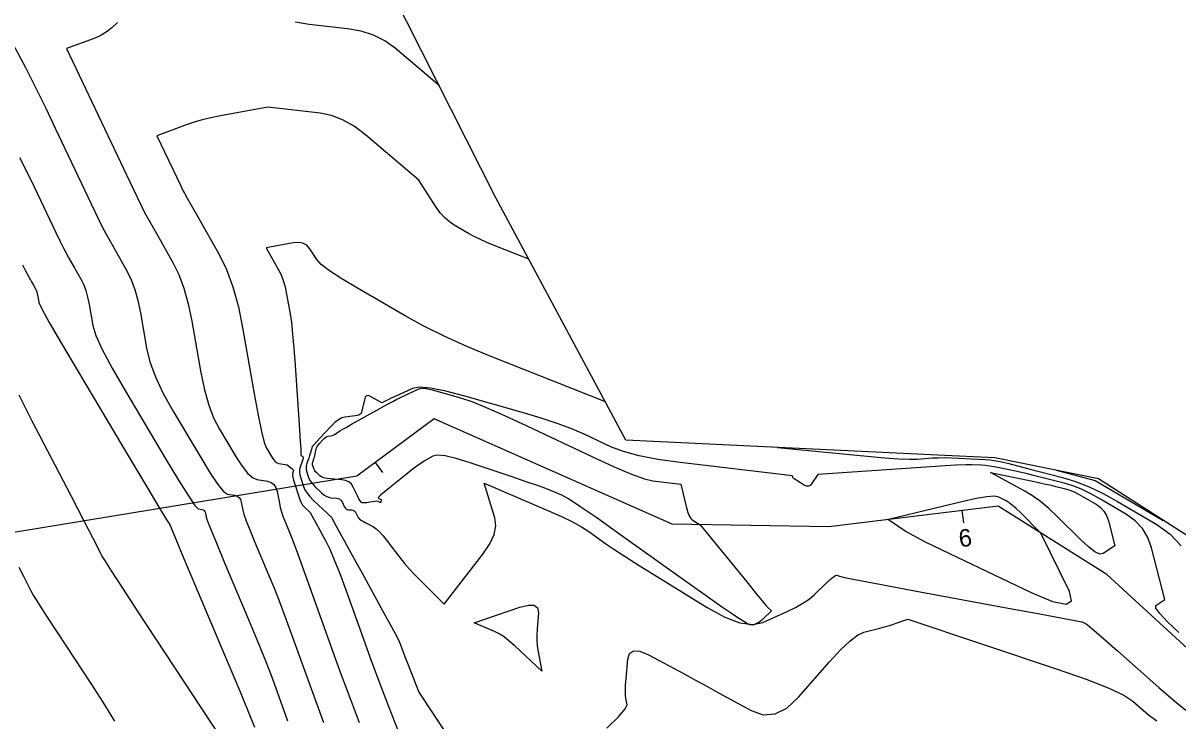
# Model space of a CAD drawing. Extents: x 1715724 to 1716561, y 394063 to 395906.
# Drawn here: x 1716279.5 to 1716371.9, y 394655.2 to 394711.1 of the extents above; entities that cross this region are included whole.
import ezdxf

# ---------------------------------------------------------------- set-up
doc = ezdxf.new("R2010")
doc.units = 0
for name, color, linetype in [('DT_X_Contour_Major', 7, 'Continuous'), ('DT_X_Contour_Minor', 7, 'Continuous'), ('DT_X_TIN_Hull', 7, 'Continuous'), ('GE_P_CL_10', 7, 'Continuous')]:
    doc.layers.add(name, color=color, linetype=linetype)

msp = doc.modelspace()

# ---------------------------------------------------------------- linework, layer by layer
at = {"layer": 'DT_X_Contour_Major'}
for points in [[(1716287.052, 394711.147), (1716286.593, 394710.724), (1716286.129, 394710.371), (1716285.659, 394710.089), (1716285.184, 394709.877), (1716282.951, 394709.057), (1716288.029, 394698.388), (1716288.615, 394697.161), (1716288.981, 394696.398), (1716289.128, 394696.099), (1716289.316, 394695.758), (1716290.247, 394694.114), (1716291.512, 394691.883), (1716291.96, 394690.965), (1716292.355, 394689.883), (1716292.696, 394688.637), (1716292.985, 394687.228), (1716293.683, 394683.252), (1716293.975, 394681.842), (1716294.326, 394680.596), (1716294.737, 394679.513), (1716295.207, 394678.594), (1716296.54, 394676.359), (1716297.018, 394675.619), (1716297.452, 394675.074), (1716297.842, 394674.725), (1716298.188, 394674.571), (1716299.054, 394674.421), (1716299.346, 394674.328), (1716299.572, 394674.162), (1716299.734, 394673.921), (1716299.832, 394673.607), (1716300.004, 394672.672), (1716300.078, 394672.323), (1716300.171, 394671.978), (1716300.284, 394671.637), (1716300.415, 394671.3), (1716300.792, 394670.407), (1716301.001, 394669.875), (1716301.346, 394668.952), (1716301.826, 394667.635), (1716302.442, 394665.927), (1716304.265, 394660.847), (1716304.957, 394658.941), (1716305.665, 394657.034), (1716306.39, 394655.126)], [(1716312.816, 394706.075), (1716309.265, 394709.099), (1716308.456, 394709.681), (1716307.55, 394710.134), (1716306.547, 394710.455), (1716305.447, 394710.647), (1716302.385, 394710.984), (1716301.27, 394711.168)], [(1716279.151, 394667.551), (1716279.518, 394666.836), (1716279.769, 394666.342), (1716279.902, 394666.07), (1716280.103, 394665.641), (1716280.293, 394665.311), (1716280.714, 394664.641), (1716281.365, 394663.633), (1716282.247, 394662.286), (1716284.906, 394658.242), (1716285.881, 394656.729), (1716286.812, 394655.225)]]:
    msp.add_lwpolyline(points, dxfattribs=at)
at = {"layer": 'DT_X_Contour_Minor'}
for points in [[(1716278.653, 394709.427), (1716279.668, 394707.533), (1716280.103, 394706.699), (1716280.646, 394705.613), (1716281.298, 394704.278), (1716282.058, 394702.693), (1716284.948, 394696.622), (1716285.479, 394695.512), (1716285.823, 394694.801), (1716285.978, 394694.49), (1716286.235, 394694.022), (1716286.934, 394692.784), (1716287.832, 394691.201), (1716288.15, 394690.549), (1716288.43, 394689.782), (1716288.673, 394688.898), (1716288.877, 394687.898), (1716289.373, 394685.076), (1716289.641, 394683.972), (1716290.076, 394682.777), (1716290.676, 394681.491), (1716291.442, 394680.114), (1716293.705, 394676.321), (1716294.475, 394675.071), (1716295.088, 394674.168), (1716295.543, 394673.61), (1716295.842, 394673.399), (1716296.428, 394673.298), (1716296.626, 394673.235), (1716296.779, 394673.122), (1716296.889, 394672.959), (1716296.955, 394672.747), (1716297.071, 394672.113), (1716297.163, 394671.778), (1716297.352, 394671.247), (1716297.636, 394670.522), (1716298.018, 394669.601), (1716299.163, 394666.886), (1716299.604, 394665.813), (1716300.069, 394664.63), (1716300.557, 394663.336), (1716301.069, 394661.932), (1716302.465, 394658.042), (1716302.995, 394656.582), (1716303.537, 394655.122)], [(1716319.983, 394692.194), (1716317.202, 394693.297), (1716316.627, 394693.535), (1716316.094, 394693.776), (1716315.602, 394694.02), (1716315.152, 394694.267), (1716314.008, 394694.93), (1716313.595, 394695.206), (1716313.215, 394695.534), (1716312.867, 394695.917), (1716312.552, 394696.352), (1716311.157, 394698.511), (1716306.892, 394702.142), (1716305.98, 394702.835), (1716305.072, 394703.359), (1716304.169, 394703.712), (1716303.27, 394703.896), (1716299.084, 394704.356), (1716295.303, 394703.663), (1716294.529, 394703.509), (1716293.826, 394703.344), (1716293.195, 394703.168), (1716292.635, 394702.981), (1716290.192, 394702.083), (1716292.105, 394698.067), (1716292.278, 394697.708), (1716292.311, 394697.648), (1716292.398, 394697.493), (1716292.635, 394697.074), (1716293.022, 394696.391), (1716293.56, 394695.444), (1716295.192, 394692.566), (1716295.77, 394691.381), (1716296.28, 394689.985), (1716296.72, 394688.377), (1716297.093, 394686.559), (1716297.994, 394681.428), (1716298.308, 394679.713), (1716298.576, 394678.415), (1716298.797, 394677.535), (1716298.972, 394677.073), (1716299.375, 394676.398), (1716299.525, 394676.173), (1716299.672, 394676.005), (1716299.817, 394675.895), (1716299.96, 394675.842), (1716300.621, 394675.728), (1716301.005, 394675.456), (1716301.074, 394675.397), (1716301.117, 394675.335), (1716301.132, 394675.27), (1716301.121, 394675.202), (1716301.056, 394675.019), (1716301.049, 394674.915), (1716301.077, 394674.743), (1716301.139, 394674.503), (1716301.235, 394674.193), (1716301.539, 394673.276), (1716301.652, 394672.963), (1716301.762, 394672.712), (1716301.87, 394672.521), (1716301.975, 394672.392), (1716302.458, 394671.934), (1716303.734, 394669.615), (1716304.039, 394668.999), (1716304.405, 394668.145), (1716304.833, 394667.052), (1716305.322, 394665.72), (1716306.711, 394661.851), (1716307.282, 394660.287), (1716307.954, 394658.496), (1716308.728, 394656.479), (1716309.603, 394654.235)], [(1716279.207, 394700.339), (1716279.842, 394699.081), (1716280.38, 394697.978), (1716282.119, 394694.326), (1716282.456, 394693.626), (1716282.692, 394693.145), (1716282.828, 394692.881), (1716283.153, 394692.286), (1716283.622, 394691.454), (1716284.152, 394690.519), (1716284.34, 394690.134), (1716284.506, 394689.68), (1716284.649, 394689.158), (1716284.77, 394688.567), (1716285.062, 394686.9), (1716285.308, 394686.102), (1716285.826, 394684.959), (1716286.615, 394683.47), (1716287.677, 394681.635), (1716290.87, 394676.282), (1716291.932, 394674.523), (1716292.724, 394673.261), (1716293.245, 394672.496), (1716293.495, 394672.228), (1716293.802, 394672.175), (1716293.906, 394672.142), (1716293.986, 394672.083), (1716294.044, 394671.997), (1716294.078, 394671.886), (1716294.139, 394671.554), (1716294.249, 394671.233), (1716294.532, 394670.517), (1716294.989, 394669.407), (1716295.62, 394667.903), (1716297.534, 394663.366), (1716298.207, 394661.751), (1716298.792, 394660.307), (1716299.288, 394659.036), (1716299.696, 394657.938), (1716300.665, 394655.237)], [(1716326.107, 394680.781), (1716316.874, 394684.443), (1716314.965, 394685.233), (1716313.194, 394686.033), (1716311.562, 394686.844), (1716310.068, 394687.665), (1716306.269, 394689.867), (1716304.996, 394690.63), (1716304.027, 394691.268), (1716303.362, 394691.78), (1716303, 394692.168), (1716302.44, 394693.034), (1716302.198, 394693.308), (1716301.895, 394693.479), (1716301.528, 394693.547), (1716301.099, 394693.512), (1716298.951, 394693.109), (1716299.946, 394691.355), (1716300.146, 394690.952), (1716300.318, 394690.494), (1716300.463, 394689.98), (1716300.582, 394689.412), (1716300.861, 394687.824), (1716300.964, 394687.12), (1716301.067, 394686.201), (1716301.169, 394685.067), (1716301.269, 394683.718), (1716301.62, 394678.55), (1716301.681, 394677.616), (1716301.717, 394677.032), (1716301.727, 394676.796), (1716301.714, 394676.511), (1716301.881, 394676.393), (1716301.905, 394676.35), (1716301.904, 394676.269), (1716301.88, 394676.152), (1716301.831, 394675.998), (1716301.668, 394675.539), (1716301.626, 394675.356), (1716301.619, 394675.152), (1716301.65, 394674.928), (1716301.717, 394674.681), (1716301.943, 394673.997), (1716302.055, 394673.737), (1716302.221, 394673.47), (1716302.44, 394673.197), (1716302.712, 394672.917), (1716303.51, 394672.16), (1716303.772, 394671.912), (1716303.961, 394671.735), (1716304.076, 394671.628), (1716304.117, 394671.592), (1716304.128, 394671.591), (1716304.132, 394671.591), (1716304.135, 394671.589), (1716304.137, 394671.587), (1716304.139, 394671.584), (1716304.143, 394671.575), (1716304.145, 394671.572), (1716304.147, 394671.57), (1716304.149, 394671.569), (1716304.152, 394671.568), (1716304.159, 394671.568), (1716304.161, 394671.567), (1716304.164, 394671.565), (1716304.167, 394671.562), (1716304.169, 394671.557), (1716304.177, 394671.542), (1716304.201, 394671.497), (1716304.268, 394671.375), (1716304.377, 394671.174), (1716304.528, 394670.895), (1716304.988, 394670.047), (1716305.219, 394669.625), (1716305.564, 394668.994), (1716306.025, 394668.155), (1716306.601, 394667.108), (1716308.292, 394664.037), (1716308.852, 394663.013), (1716309.266, 394662.244), (1716309.533, 394661.731), (1716309.653, 394661.472), (1716309.778, 394661.123), (1716309.844, 394660.947), (1716309.947, 394660.678), (1716310.087, 394660.317), (1716310.264, 394659.864), (1716311.178, 394657.534), (1716315.911, 394650.33)], [(1716279.433, 394691.741), (1716279.562, 394691.489), (1716279.678, 394691.271), (1716279.969, 394690.739), (1716280.072, 394690.55), (1716280.163, 394690.385), (1716280.242, 394690.243), (1716280.309, 394690.124), (1716280.472, 394689.836), (1716280.53, 394689.718), (1716280.581, 394689.578), (1716280.625, 394689.418), (1716280.662, 394689.236), (1716280.752, 394688.724), (1716280.975, 394688.232), (1716281.576, 394687.14), (1716282.555, 394685.448), (1716283.912, 394683.156), (1716288.035, 394676.244), (1716289.39, 394673.976), (1716290.36, 394672.355), (1716290.946, 394671.382), (1716291.149, 394671.056), (1716291.176, 394671.052), (1716291.186, 394671.049), (1716291.193, 394671.043), (1716291.198, 394671.036), (1716291.201, 394671.025), (1716291.207, 394670.996), (1716291.334, 394670.688), (1716291.713, 394669.786), (1716292.342, 394668.292), (1716293.222, 394666.204), (1716295.904, 394659.845), (1716296.81, 394657.688), (1716297.515, 394655.985), (1716298.019, 394654.737)], [(1716372.026, 394662.316), (1716371.099, 394663.184), (1716370.482, 394663.834), (1716370.174, 394664.264), (1716370.176, 394664.475), (1716370.904, 394664.949), (1716369.838, 394669.084), (1716369.541, 394669.916), (1716369.106, 394670.642), (1716368.532, 394671.262), (1716367.821, 394671.775), (1716365.74, 394673.001), (1716364.972, 394673.425), (1716364.231, 394673.777), (1716363.517, 394674.058), (1716362.828, 394674.268), (1716361.028, 394674.732), (1716360.383, 394674.896), (1716359.798, 394675.038), (1716359.274, 394675.158), (1716358.809, 394675.257), (1716357.651, 394675.493), (1716357.236, 394675.572), (1716356.857, 394675.634), (1716356.516, 394675.678), (1716356.213, 394675.703), (1716355.453, 394675.748), (1716354.983, 394675.747), (1716354.143, 394675.711), (1716352.933, 394675.64), (1716351.352, 394675.534), (1716343.11, 394674.956), (1716342.613, 394674.204), (1716342.496, 394674.078), (1716342.358, 394674.02), (1716342.199, 394674.032), (1716342.02, 394674.113), (1716341.514, 394674.422), (1716341.346, 394674.527), (1716341.225, 394674.611), (1716341.149, 394674.675), (1716341.118, 394674.718), (1716341.082, 394674.868), (1716332.1, 394675.928), (1716330.313, 394676.175), (1716328.8, 394676.463), (1716327.563, 394676.792), (1716326.6, 394677.161), (1716324.4, 394678.2), (1716323.467, 394678.602), (1716322.317, 394679.027), (1716320.951, 394679.477), (1716319.368, 394679.951), (1716314.858, 394681.245), (1716313.327, 394681.646), (1716312.116, 394681.879), (1716311.226, 394681.944), (1716310.656, 394681.84), (1716309.563, 394681.339), (1716309.194, 394681.17), (1716308.907, 394681.038), (1716308.703, 394680.944), (1716308.58, 394680.888), (1716308.2, 394680.712), (1716307.305, 394681.212), (1716307.13, 394681.276), (1716306.99, 394681.254), (1716306.884, 394681.146), (1716306.813, 394680.952), (1716306.56, 394679.846), (1716306.4, 394679.742), (1716306.341, 394679.719), (1716306.232, 394679.694), (1716306.074, 394679.667), (1716305.865, 394679.639), (1716305.243, 394679.561), (1716304.998, 394679.492), (1716304.73, 394679.344), (1716304.44, 394679.117), (1716304.126, 394678.811), (1716303.26, 394677.889), (1716302.975, 394677.581), (1716302.769, 394677.349), (1716302.642, 394677.193), (1716302.595, 394677.112), (1716302.575, 394677), (1716302.565, 394676.953), (1716302.535, 394676.837), (1716302.514, 394676.767), (1716302.454, 394676.57), (1716302.428, 394676.488), (1716302.396, 394676.39), (1716302.357, 394676.277), (1716302.312, 394676.148), (1716302.182, 394675.782), (1716302.147, 394675.641), (1716302.138, 394675.492), (1716302.155, 394675.335), (1716302.198, 394675.17), (1716302.347, 394674.718), (1716302.421, 394674.546), (1716302.53, 394674.37), (1716302.675, 394674.19), (1716302.855, 394674.005), (1716303.382, 394673.505), (1716303.576, 394673.34), (1716303.762, 394673.218), (1716303.942, 394673.14), (1716304.115, 394673.105), (1716304.566, 394673.071), (1716304.721, 394673.042), (1716304.851, 394672.983), (1716304.953, 394672.894), (1716305.029, 394672.774), (1716305.196, 394672.412), (1716305.264, 394672.293), (1716305.342, 394672.207), (1716305.43, 394672.154), (1716305.529, 394672.134), (1716305.804, 394672.125), (1716305.902, 394672.109), (1716305.987, 394672.068), (1716306.06, 394672.001), (1716306.121, 394671.909), (1716306.267, 394671.629), (1716306.32, 394671.533), (1716306.371, 394671.457), (1716306.418, 394671.399), (1716306.463, 394671.36), (1716306.579, 394671.281), (1716306.641, 394671.243), (1716306.739, 394671.189), (1716306.874, 394671.117), (1716307.045, 394671.029), (1716307.551, 394670.771), (1716307.763, 394670.625), (1716308.02, 394670.384), (1716308.323, 394670.045), (1716308.671, 394669.61), (1716309.659, 394668.321), (1716310.035, 394667.846), (1716310.424, 394667.389), (1716310.826, 394666.949), (1716311.24, 394666.527), (1716313.201, 394664.597), (1716316.292, 394668.589), (1716316.849, 394669.411), (1716317.194, 394670.169), (1716317.328, 394670.861), (1716317.25, 394671.488), (1716316.392, 394674.263), (1716321.552, 394672.064), (1716322.583, 394671.606), (1716323.466, 394671.175), (1716324.201, 394670.769), (1716324.787, 394670.391), (1716326.154, 394669.415), (1716326.791, 394668.979), (1716327.679, 394668.4), (1716328.817, 394667.68), (1716330.206, 394666.818), (1716334.242, 394664.33), (1716335.657, 394663.554), (1716336.875, 394663.094), (1716337.897, 394662.949), (1716338.721, 394663.119), (1716340.658, 394663.991), (1716341.338, 394664.321), (1716341.926, 394664.656), (1716342.422, 394664.996), (1716342.827, 394665.342), (1716343.782, 394666.269), (1716344.104, 394666.57), (1716344.356, 394666.775), (1716344.535, 394666.885), (1716344.644, 394666.9), (1716344.838, 394666.813), (1716345.26, 394666.718), (1716346.381, 394666.499), (1716348.2, 394666.156), (1716350.717, 394665.688), (1716358.362, 394664.276), (1716360.88, 394663.809), (1716362.703, 394663.468), (1716363.829, 394663.252), (1716364.258, 394663.162), (1716364.476, 394663.089), (1716364.702, 394662.928), (1716365.216, 394662.5), (1716366.02, 394661.806), (1716367.112, 394660.845), (1716370.409, 394657.927), (1716371.572, 394656.925), (1716372.587, 394656.111)], [(1716279.136, 394681.329), (1716280.198, 394679.267), (1716283.299, 394673.277), (1716284.321, 394671.302), (1716285.061, 394669.87), (1716285.52, 394668.98), (1716285.696, 394668.632), (1716285.791, 394668.429), (1716285.999, 394668.094), (1716286.55, 394667.241), (1716287.446, 394665.87), (1716288.685, 394663.982), (1716295.271, 394653.963)], [(1716302.832, 394676.433), (1716302.844, 394676.477), (1716302.874, 394676.617), (1716302.941, 394676.989), (1716302.972, 394677.095), (1716303.027, 394677.206), (1716303.106, 394677.322), (1716303.21, 394677.443), (1716303.518, 394677.771), (1716303.63, 394677.88), (1716303.733, 394677.961), (1716303.828, 394678.014), (1716303.916, 394678.038), (1716304.137, 394678.066), (1716304.225, 394678.085), (1716304.321, 394678.12), (1716304.426, 394678.172), (1716304.541, 394678.241), (1716304.858, 394678.447), (1716305.041, 394678.559), (1716305.352, 394678.739), (1716305.791, 394678.989), (1716308.044, 394680.248), (1716308.618, 394680.567), (1716309.077, 394680.817), (1716309.421, 394680.998), (1716309.649, 394681.112), (1716310.768, 394681.627), (1716311.195, 394681.822), (1716311.417, 394681.863), (1716311.765, 394681.838), (1716312.237, 394681.747), (1716312.834, 394681.59), (1716314.594, 394681.085), (1716315.415, 394680.804), (1716316.56, 394680.34), (1716318.028, 394679.692), (1716319.819, 394678.862), (1716325.027, 394676.402), (1716326.796, 394675.588), (1716328.197, 394674.99), (1716329.231, 394674.609), (1716329.897, 394674.444), (1716332.148, 394674.178), (1716332.603, 394672.293), (1716332.704, 394671.93), (1716332.815, 394671.647), (1716332.935, 394671.445), (1716333.064, 394671.323), (1716333.687, 394670.944), (1716337.423, 394666.363), (1716338.131, 394665.497), (1716338.653, 394664.864), (1716338.989, 394664.464), (1716339.14, 394664.296), (1716339.412, 394664.056), (1716338.762, 394663.426), (1716338.627, 394663.302), (1716338.499, 394663.199), (1716338.38, 394663.118), (1716338.268, 394663.058), (1716337.979, 394662.928), (1716337.856, 394662.903), (1716337.704, 394662.924), (1716337.522, 394662.993), (1716337.311, 394663.108), (1716336.71, 394663.479), (1716336.269, 394663.775), (1716335.397, 394664.384), (1716334.093, 394665.306), (1716332.358, 394666.541), (1716327.157, 394670.254), (1716325.411, 394671.489), (1716324.073, 394672.409), (1716323.145, 394673.015), (1716322.624, 394673.307), (1716321.781, 394673.666), (1716321.348, 394673.837), (1716320.68, 394674.078), (1716319.776, 394674.39), (1716318.638, 394674.774), (1716315.29, 394675.891), (1716314.161, 394676.239), (1716313.285, 394676.446), (1716312.661, 394676.511), (1716312.289, 394676.435), (1716311.636, 394676.045), (1716311.359, 394675.867), (1716311.019, 394675.627), (1716310.615, 394675.326), (1716310.147, 394674.962), (1716308.817, 394673.909), (1716308.386, 394673.561), (1716308.093, 394673.305), (1716307.937, 394673.142), (1716307.918, 394673.071), (1716308.151, 394672.957), (1716308.125, 394672.766), (1716308.115, 394672.733), (1716308.097, 394672.715), (1716308.071, 394672.713), (1716308.036, 394672.727), (1716307.853, 394672.829), (1716307.245, 394672.737), (1716307.122, 394672.72), (1716307.013, 394672.708), (1716306.919, 394672.702), (1716306.839, 394672.702), (1716306.643, 394672.708), (1716306.564, 394672.744), (1716306.472, 394672.846), (1716306.367, 394673.014), (1716306.249, 394673.249), (1716305.919, 394673.963), (1716305.769, 394674.201), (1716305.566, 394674.378), (1716305.311, 394674.494), (1716305.003, 394674.55), (1716304.113, 394674.618), (1716303.809, 394674.651), (1716303.564, 394674.701), (1716303.379, 394674.768), (1716303.253, 394674.85), (1716302.998, 394675.093), (1716302.91, 394675.182), (1716302.84, 394675.27), (1716302.787, 394675.355), (1716302.752, 394675.439), (1716302.679, 394675.658), (1716302.658, 394675.738), (1716302.65, 394675.814), (1716302.654, 394675.887), (1716302.671, 394675.955), (1716302.734, 394676.132), (1716302.756, 394676.195), (1716302.775, 394676.25), (1716302.791, 394676.297), (1716302.803, 394676.337), (1716302.832, 394676.433)], [(1716339.879, 394677.132), (1716347.061, 394676.436), (1716348.465, 394676.31), (1716349.599, 394676.228), (1716350.462, 394676.192), (1716351.056, 394676.202), (1716352.279, 394676.288), (1716352.754, 394676.311), (1716353.263, 394676.318), (1716353.806, 394676.309), (1716354.382, 394676.282), (1716355.964, 394676.19), (1716356.498, 394676.156), (1716356.914, 394676.125), (1716357.212, 394676.097), (1716357.392, 394676.071), (1716357.714, 394676.005), (1716357.948, 394675.951), (1716358.405, 394675.837), (1716359.088, 394675.663), (1716359.995, 394675.43), (1716362.714, 394674.729), (1716363.754, 394674.413), (1716364.833, 394673.988), (1716365.952, 394673.455), (1716367.111, 394672.815), (1716370.254, 394670.964), (1716371.329, 394670.189), (1716372.195, 394669.253)], [(1716356.93, 394675.115), (1716360.059, 394674.478), (1716360.687, 394674.347), (1716361.23, 394674.23), (1716361.688, 394674.126), (1716362.061, 394674.034), (1716362.943, 394673.807), (1716363.28, 394673.704), (1716363.63, 394673.567), (1716363.992, 394673.394), (1716364.368, 394673.186), (1716365.387, 394672.586), (1716365.735, 394672.335), (1716366.016, 394672.032), (1716366.229, 394671.676), (1716366.375, 394671.268), (1716366.897, 394669.244), (1716365.952, 394668.628), (1716365.687, 394668.6), (1716365.298, 394668.778), (1716364.785, 394669.163), (1716364.147, 394669.754), (1716362.282, 394671.607), (1716361.595, 394672.254), (1716360.936, 394672.808), (1716360.303, 394673.267), (1716359.697, 394673.632), (1716356.93, 394675.115)], [(1716362.183, 394675.298), (1716365.329, 394674.487), (1716370.774, 394671.28)], [(1716359.327, 394671.912), (1716358.991, 394672.233), (1716358.689, 394672.496), (1716358.42, 394672.7), (1716358.186, 394672.846), (1716357.605, 394673.157), (1716357.257, 394673.221), (1716356.648, 394673.18), (1716355.778, 394673.033), (1716354.647, 394672.781), (1716348.76, 394671.359), (1716350.189, 394670.398), (1716350.709, 394670.098), (1716351.656, 394669.611), (1716353.03, 394668.935), (1716354.832, 394668.072), (1716360.206, 394665.52), (1716361.908, 394664.807), (1716362.984, 394664.584), (1716363.434, 394664.851), (1716363.258, 394665.607), (1716360.974, 394670.276), (1716359.327, 394671.912)], [(1716315.597, 394663.083), (1716319.259, 394664.339), (1716319.94, 394664.513), (1716320.415, 394664.498), (1716320.684, 394664.292), (1716320.747, 394663.897), (1716320.639, 394662.589), (1716320.612, 394662.115), (1716320.612, 394661.675), (1716320.639, 394661.268), (1716320.694, 394660.895), (1716321.013, 394659.231), (1716318.86, 394661.24), (1716318.413, 394661.635), (1716317.993, 394661.96), (1716317.601, 394662.213), (1716317.236, 394662.396), (1716315.597, 394663.083)], [(1716326.23, 394654.663), (1716327.151, 394655.572), (1716327.689, 394656.196), (1716327.843, 394656.536), (1716327.742, 394657.064), (1716327.715, 394657.31), (1716327.709, 394657.653), (1716327.725, 394658.092), (1716327.763, 394658.628), (1716327.891, 394660.186), (1716328.032, 394660.645), (1716328.357, 394660.853), (1716328.867, 394660.811), (1716329.561, 394660.518), (1716331.659, 394659.403), (1716332.468, 394658.971), (1716333.324, 394658.509), (1716334.226, 394658.018), (1716335.174, 394657.498), (1716337.764, 394656.071), (1716338.73, 394655.737), (1716339.687, 394655.802), (1716340.632, 394656.267), (1716341.568, 394657.133), (1716344.05, 394659.974), (1716344.919, 394660.921), (1716345.666, 394661.63), (1716346.291, 394662.101), (1716346.793, 394662.334), (1716347.969, 394662.639), (1716348.382, 394662.749), (1716348.74, 394662.85), (1716349.044, 394662.943), (1716349.293, 394663.026), (1716350.324, 394663.395), (1716362.285, 394659.377), (1716364.585, 394658.573), (1716366.362, 394657.88), (1716367.615, 394657.299), (1716368.343, 394656.83), (1716369.587, 394655.729), (1716370.241, 394655.236)]]:
    msp.add_lwpolyline(points, dxfattribs=at)
at = {"layer": 'DT_X_TIN_Hull'}
msp.add_lwpolyline([(1716374.782, 394668.715), (1716365.574, 394674.608), (1716357.292, 394676.294), (1716352.716, 394676.514), (1716327.751, 394677.716), (1716317.343, 394697.112), (1716309.021, 394713.588), (1716295.593, 394725.636), (1716283.618, 394745.304), (1716279.618, 394747.622), (1716265.79, 394771.45)], dxfattribs=at)
at = {"layer": 'GE_P_CL_10'}
for p, q in [((1716312.41, 394679.432), (1716306.2, 394674.833)), ((1716331.464, 394670.979), (1716312.41, 394679.432)), ((1716307.672, 394675.923), (1716308.267, 394675.12)), ((1716306.2, 394674.833), (1716217.392, 394660.231)), ((1716357.545, 394672.43), (1716344.008, 394670.78)), ((1716354.643, 394672.076), (1716354.764, 394671.084)), ((1716366.245, 394666.965), (1716357.545, 394672.43)), ((1716344.008, 394670.78), (1716331.464, 394670.979)), ((1716390.541, 394644.647), (1716366.245, 394666.965))]:
    msp.add_line(p, q, dxfattribs=at)

# ---------------------------------------------------------------- texts
msp.add_text('9', height=1.4, rotation=186.94908, dxfattribs=at).set_placement((1716355.35, 394670.651))

doc.saveas('drawing.dxf')
